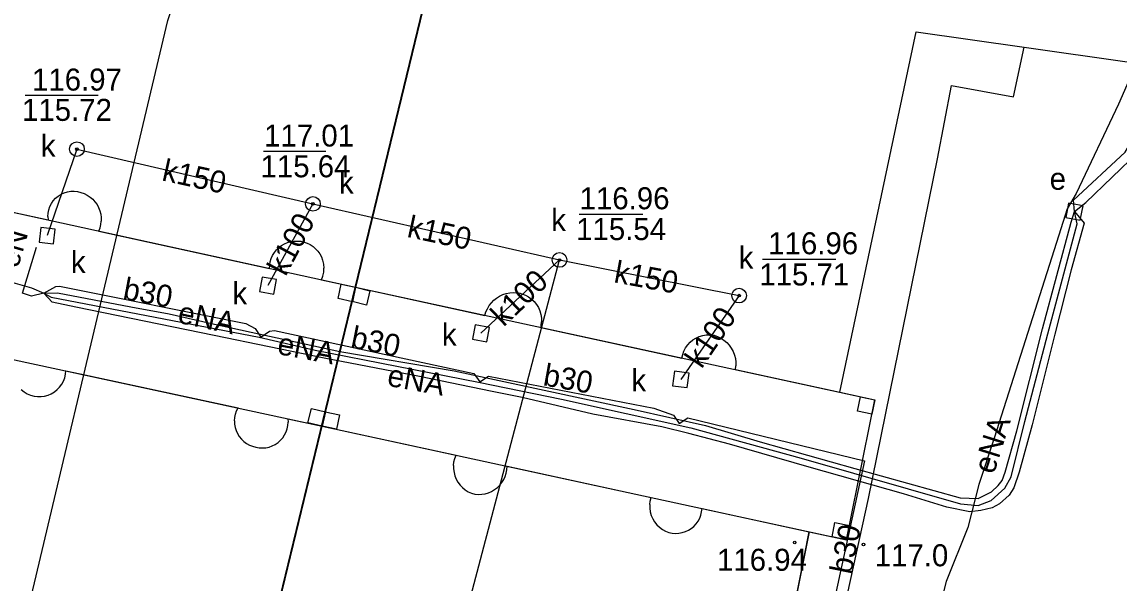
# Model space of a CAD drawing. Extents: x 6424617 to 6425697, y 5665845 to 5667190.
# Drawn here: x 6425428.81 to 6425466.22, y 5666525 to 5666544.12 of the extents above; entities that cross this region are included whole.
import ezdxf

# ---------------------------------------------------------------- set-up
doc = ezdxf.new("R2010")
doc.units = 0
for name, color, linetype in [('Warstwa 1', 7, 'Continuous'), ('Warstwa 12', 7, 'Continuous'), ('Warstwa 13', 7, 'Continuous'), ('Warstwa 14', 7, 'Continuous'), ('Warstwa 15', 7, 'Continuous'), ('Warstwa 25', 7, 'Continuous'), ('Warstwa 33', 7, 'Continuous'), ('Warstwa 4', 7, 'Continuous'), ('Warstwa 5', 7, 'Continuous'), ('Warstwa 6', 7, 'Continuous'), ('Warstwa 8', 7, 'Continuous'), ('Warstwa 9', 7, 'Continuous')]:
    doc.layers.add(name, color=color, linetype=linetype)

msp = doc.modelspace()

# ---------------------------------------------------------------- linework, layer by layer
at = {"layer": 'Warstwa 1'}
msp.add_line((6425426.498, 5666478.714), (6425446.546, 5666561.317), dxfattribs=at)
msp.add_line((6425426.498, 5666478.714), (6425446.546, 5666561.317), dxfattribs=at)
at = {"layer": 'Warstwa 12'}
for points in [[(6425380.898, 5666313.781), (6425400.051, 5666402.067), (6425408.909, 5666440.823), (6425416.154, 5666473.488), (6425420.109, 5666487.161), (6425420.685, 5666489.264), (6425421.019, 5666490.41), (6425433.788, 5666544.17), (6425438.345, 5666557.965), (6425447.158, 5666555.689), (6425449.696, 5666562.969)], [(6425464.702, 5666537.656), (6425464.675, 5666538.044), (6425466.427, 5666539.686), (6425466.835, 5666540.361), (6425473.065, 5666562.687)], [(6425464.702, 5666537.656), (6425465.091, 5666537.962), (6425466.887, 5666539.7), (6425467.175, 5666540.317), (6425473.425, 5666562.682)], [(6425467.242, 5666545.086), (6425466.733, 5666542.702), (6425466.567, 5666542.144), (6425466.207, 5666541.318), (6425464.76, 5666538.276), (6425464.45, 5666537.751), (6425464.173, 5666536.853), (6425461.959, 5666529.939), (6425461.44, 5666528.355), (6425461.062, 5666526.89), (6425460.33, 5666525.048), (6425459.721, 5666522.676), (6425458.623, 5666517.819), (6425457.064, 5666510.497), (6425456.807, 5666509.92), (6425456.473, 5666509.544), (6425455.928, 5666509.171), (6425455.043, 5666508.721), (6425454.006, 5666508.154), (6425449.423, 5666506.309), (6425447.519, 5666505.982), (6425446.295, 5666505.707), (6425444.189, 5666503.512), (6425436.064, 5666495.689)], [(6425430.685, 5666539.787), (6425429.669, 5666536.839)], [(6425430.685, 5666539.787), (6425438.733, 5666537.92), (6425447.141, 5666536.008)], [(6425416.711, 5666528.745), (6425418.224, 5666538.167), (6425429.138, 5666535.055), (6425429.552, 5666534.882)], [(6425438.733, 5666537.92), (6425437.2, 5666535.138)], [(6425464.702, 5666537.656), (6425465.028, 5666537.262), (6425464.588, 5666535.668), (6425464.032, 5666533.474), (6425463.255, 5666530.393), (6425462.815, 5666528.779), (6425462.639, 5666528.241), (6425462.476, 5666527.993), (6425462.142, 5666527.697), (6425461.9, 5666527.56), (6425461.509, 5666527.464), (6425461.139, 5666527.419), (6425460.351, 5666527.588), (6425458.876, 5666528.036), (6425455.657, 5666528.945), (6425452.936, 5666529.728), (6425451.55, 5666530.095), (6425450.633, 5666530.326), (6425448.278, 5666530.754), (6425445.864, 5666531.323), (6425444.847, 5666531.526), (6425442.363, 5666532.036), (6425439.12, 5666532.665), (6425435.359, 5666533.43), (6425430.65, 5666534.397), (6425429.842, 5666534.567), (6425429.552, 5666534.882)], [(6425429.552, 5666534.882), (6425429.804, 5666534.737), (6425436.898, 5666533.372), (6425438.813, 5666532.939), (6425444.38, 5666531.841), (6425447.204, 5666531.267), (6425451.622, 5666530.284), (6425455.38, 5666529.248), (6425460.812, 5666527.693), (6425461.421, 5666527.635), (6425461.863, 5666527.81), (6425462.329, 5666528.235), (6425462.543, 5666528.612), (6425463.006, 5666530.506), (6425463.792, 5666533.487), (6425464.798, 5666537.245), (6425464.702, 5666537.656)], [(6425429.552, 5666534.882), (6425430.016, 5666534.885), (6425432.52, 5666534.415), (6425433.828, 5666534.169), (6425435.373, 5666533.82), (6425439.653, 5666532.888), (6425443.545, 5666532.231), (6425449.69, 5666530.917), (6425452.123, 5666530.368), (6425453.987, 5666529.805), (6425457.216, 5666528.906), (6425460.805, 5666527.903), (6425461.424, 5666527.875), (6425461.877, 5666528.1), (6425462.1, 5666528.317), (6425462.232, 5666528.486), (6425462.335, 5666528.774), (6425462.732, 5666530.19), (6425463.614, 5666533.659), (6425464.586, 5666537.298), (6425464.702, 5666537.656)], [(6425429.552, 5666534.882), (6425429.137, 5666534.78), (6425428.826, 5666534.879), (6425429.305, 5666536.443)], [(6425407.795, 5666377.502), (6425413.082, 5666398.74), (6425423.493, 5666441.827), (6425434.167, 5666486.832), (6425447.141, 5666536.008)], [(6425447.141, 5666536.008), (6425444.461, 5666533.51)], [(6425447.141, 5666536.008), (6425453.267, 5666534.794)], [(6425429.552, 5666534.882), (6425429.964, 5666535.101), (6425430.085, 5666535.121), (6425436.44, 5666533.848), (6425436.761, 5666533.671), (6425436.96, 5666533.38)], [(6425453.267, 5666534.794), (6425451.282, 5666531.938)], [(6425436.96, 5666533.38), (6425437.252, 5666533.579), (6425437.427, 5666533.606), (6425444.225, 5666532.14), (6425444.428, 5666531.851)], [(6425444.428, 5666531.851), (6425444.717, 5666532.053), (6425450.353, 5666530.96), (6425451.023, 5666530.723), (6425451.218, 5666530.429)], [(6425451.218, 5666530.429), (6425451.512, 5666530.624), (6425457.542, 5666529.162), (6425456.393, 5666523.876), (6425454.252, 5666517.66)]]:
    msp.add_lwpolyline(points, dxfattribs=at)
at = {"layer": 'Warstwa 13'}
msp.add_circle((6425457.511, 5666526.308), 0.045, dxfattribs=at)
at = {"layer": 'Warstwa 14'}
for p, q in [((6425428.917, 5666541.627), (6425431.409, 5666541.627)), ((6425437.051, 5666539.714), (6425439.167, 5666539.714)), ((6425447.814, 5666537.573), (6425449.985, 5666537.573)), ((6425454.06, 5666536.032), (6425456.569, 5666536.032))]:
    msp.add_line(p, q, dxfattribs=at)
for centre in [(6425430.685, 5666539.787), (6425438.733, 5666537.92), (6425447.141, 5666536.008), (6425453.267, 5666534.794)]:
    msp.add_circle(centre, 0.045, dxfattribs=at)
at = {"layer": 'Warstwa 25'}
msp.add_circle((6425455.161, 5666526.381), 0.045, dxfattribs=at)
at = {"layer": 'Warstwa 33'}
for p, q in [((6425426.407, 5666538.096), (6425440.186, 5666535.076)), ((6425439.048, 5666530.345), (6425440.186, 5666535.076)), ((6425439.048, 5666530.345), (6425440.186, 5666535.076)), ((6425440.186, 5666535.076), (6425457.898, 5666531.242)), ((6425425.351, 5666533.3), (6425439.048, 5666530.345)), ((6425456.925, 5666526.467), (6425457.898, 5666531.242)), ((6425439.048, 5666530.345), (6425456.925, 5666526.467))]:
    msp.add_line(p, q, dxfattribs=at)
for points in [[(6425440.079, 5666534.587), (6425439.59, 5666534.694), (6425439.697, 5666535.183), (6425440.186, 5666535.076)], [(6425440.673, 5666534.959), (6425440.556, 5666534.472), (6425440.069, 5666534.589), (6425440.186, 5666535.076)], [(6425457.792, 5666530.754), (6425457.304, 5666530.86), (6425457.41, 5666531.348), (6425457.898, 5666531.242)], [(6425438.561, 5666530.462), (6425438.678, 5666530.949), (6425439.165, 5666530.832), (6425439.048, 5666530.345)], [(6425439.154, 5666530.833), (6425439.642, 5666530.727), (6425439.536, 5666530.239), (6425439.048, 5666530.345)], [(6425456.435, 5666526.567), (6425456.535, 5666527.057), (6425457.025, 5666526.957), (6425456.925, 5666526.467)]]:
    msp.add_lwpolyline(points, close=True, dxfattribs=at)
at = {"layer": 'Warstwa 4'}
for points in [[(6425464.9, 5666537.363), (6425464.995, 5666537.854), (6425464.504, 5666537.949), (6425464.409, 5666537.458)], [(6425429.45, 5666537.116), (6425429.392, 5666536.62), (6425429.888, 5666536.562), (6425429.946, 5666537.058)], [(6425436.997, 5666535.428), (6425436.91, 5666534.935), (6425437.403, 5666534.848), (6425437.49, 5666535.341)], [(6425444.752, 5666533.71), (6425444.261, 5666533.801), (6425444.17, 5666533.31), (6425444.661, 5666533.219)], [(6425451.068, 5666532.22), (6425451, 5666531.724), (6425451.496, 5666531.656), (6425451.564, 5666532.152)]]:
    msp.add_lwpolyline(points, close=True, dxfattribs=at)
for centre in [(6425430.685, 5666539.787), (6425438.733, 5666537.92), (6425447.141, 5666536.008), (6425453.267, 5666534.794)]:
    msp.add_circle(centre, 0.25, dxfattribs=at)
at = {"layer": 'Warstwa 6'}
for points in [[(6425412.836, 5666481.999), (6425414.841, 5666481.544), (6425426.498, 5666478.714), (6425446.546, 5666561.317), (6425434.889, 5666564.147), (6425438.183, 5666577.748), (6425436.256, 5666578.862)], [(6425445.943, 5666473.999), (6425449.122, 5666487.121), (6425471.272, 5666493.575), (6425489.08, 5666567.113), (6425449.85, 5666574.917), (6425446.546, 5666561.317), (6425426.498, 5666478.714)]]:
    msp.add_lwpolyline(points, close=True, dxfattribs=at)
for points in [[(6425456.703, 5666531.501), (6425459.304, 5666543.782), (6425462.987, 5666543.257), (6425466.579, 5666542.746), (6425468.099, 5666550.832), (6425426.818, 5666561.105), (6425426.239, 5666561.299), (6425425.664, 5666561.506), (6425425.094, 5666561.725), (6425424.53, 5666561.957), (6425423.97, 5666562.202), (6425423.417, 5666562.46), (6425422.869, 5666562.73), (6425422.328, 5666563.012), (6425421.793, 5666563.306)], [(6425455.66, 5666526.741), (6425453.028, 5666513.652), (6425431.999, 5666496.905), (6425431.589, 5666496.517), (6425431.195, 5666496.111), (6425430.819, 5666495.689), (6425430.462, 5666495.252), (6425430.123, 5666494.799), (6425429.805, 5666494.333), (6425429.506, 5666493.853), (6425429.229, 5666493.361), (6425428.972, 5666492.857), (6425428.722, 5666492.217)]]:
    msp.add_lwpolyline(points, dxfattribs=at)
at = {"layer": 'Warstwa 8'}
for p, q in [((6425456.703, 5666531.501), (6425459.304, 5666543.782)), ((6425459.304, 5666543.782), (6425462.987, 5666543.257)), ((6425462.987, 5666543.257), (6425466.579, 5666542.746)), ((6425429.879, 5666538.028), (6425429.958, 5666538.113)), ((6425429.958, 5666538.113), (6425430.047, 5666538.187)), ((6425430.047, 5666538.187), (6425430.145, 5666538.249)), ((6425430.145, 5666538.249), (6425430.25, 5666538.297)), ((6425430.25, 5666538.297), (6425430.361, 5666538.331)), ((6425430.361, 5666538.331), (6425430.475, 5666538.349)), ((6425430.475, 5666538.349), (6425430.591, 5666538.352)), ((6425430.591, 5666538.352), (6425430.706, 5666538.34)), ((6425430.706, 5666538.34), (6425430.819, 5666538.312)), ((6425430.819, 5666538.312), (6425430.93, 5666538.272)), ((6425430.93, 5666538.272), (6425431.034, 5666538.219)), ((6425431.034, 5666538.219), (6425431.132, 5666538.154)), ((6425431.132, 5666538.154), (6425431.221, 5666538.078)), ((6425426.407, 5666538.096), (6425429.698, 5666537.375)), ((6425429.722, 5666537.72), (6425429.761, 5666537.829)), ((6425429.761, 5666537.829), (6425429.813, 5666537.932)), ((6425429.813, 5666537.932), (6425429.879, 5666538.028)), ((6425431.221, 5666538.078), (6425431.3, 5666537.991)), ((6425431.3, 5666537.991), (6425431.369, 5666537.895)), ((6425431.369, 5666537.895), (6425431.425, 5666537.792)), ((6425431.425, 5666537.792), (6425431.468, 5666537.683)), ((6425429.691, 5666537.491), (6425429.699, 5666537.606)), ((6425429.691, 5666537.491), (6425429.698, 5666537.375)), ((6425429.699, 5666537.606), (6425429.722, 5666537.72)), ((6425431.468, 5666537.683), (6425431.497, 5666537.569)), ((6425431.497, 5666537.569), (6425431.513, 5666537.453)), ((6425431.513, 5666537.453), (6425431.514, 5666537.335)), ((6425431.434, 5666536.994), (6425431.475, 5666537.104)), ((6425431.434, 5666536.994), (6425433.091, 5666536.631)), ((6425431.475, 5666537.104), (6425431.501, 5666537.219)), ((6425431.501, 5666537.219), (6425431.514, 5666537.335)), ((6425433.091, 5666536.631), (6425437.251, 5666535.72)), ((6425437.867, 5666536.602), (6425437.977, 5666536.634)), ((6425437.977, 5666536.634), (6425438.09, 5666536.652)), ((6425438.09, 5666536.652), (6425438.205, 5666536.655)), ((6425438.205, 5666536.655), (6425438.319, 5666536.645)), ((6425438.319, 5666536.645), (6425438.431, 5666536.62)), ((6425438.431, 5666536.62), (6425438.539, 5666536.582)), ((6425437.358, 5666536.162), (6425437.417, 5666536.26)), ((6425437.417, 5666536.26), (6425437.489, 5666536.35)), ((6425437.489, 5666536.35), (6425437.571, 5666536.43)), ((6425437.571, 5666536.43), (6425437.662, 5666536.5)), ((6425437.662, 5666536.5), (6425437.761, 5666536.557)), ((6425437.761, 5666536.557), (6425437.867, 5666536.602)), ((6425438.539, 5666536.582), (6425438.642, 5666536.531)), ((6425438.642, 5666536.531), (6425438.737, 5666536.467)), ((6425438.737, 5666536.467), (6425438.824, 5666536.392)), ((6425438.824, 5666536.392), (6425438.901, 5666536.307)), ((6425438.901, 5666536.307), (6425438.967, 5666536.213)), ((6425437.257, 5666535.835), (6425437.277, 5666535.948)), ((6425437.277, 5666535.948), (6425437.311, 5666536.057)), ((6425437.311, 5666536.057), (6425437.358, 5666536.162)), ((6425438.967, 5666536.213), (6425439.02, 5666536.111)), ((6425439.02, 5666536.111), (6425439.061, 5666536.004)), ((6425439.061, 5666536.004), (6425439.094, 5666535.87)), ((6425439.094, 5666535.87), (6425439.107, 5666535.733)), ((6425437.251, 5666535.72), (6425437.257, 5666535.835)), ((6425439.073, 5666535.46), (6425439.1, 5666535.595)), ((6425439.1, 5666535.595), (6425439.107, 5666535.733)), ((6425439.026, 5666535.33), (6425439.073, 5666535.46)), ((6425439.026, 5666535.33), (6425440.186, 5666535.076)), ((6425440.186, 5666535.076), (6425444.599, 5666534.121)), ((6425444.995, 5666534.712), (6425445.098, 5666534.776)), ((6425445.098, 5666534.776), (6425445.208, 5666534.828)), ((6425445.208, 5666534.828), (6425445.323, 5666534.865)), ((6425445.323, 5666534.865), (6425445.442, 5666534.889)), ((6425445.442, 5666534.889), (6425445.562, 5666534.898)), ((6425445.562, 5666534.898), (6425445.683, 5666534.893)), ((6425445.683, 5666534.893), (6425445.803, 5666534.873)), ((6425445.803, 5666534.873), (6425445.862, 5666534.858)), ((6425445.862, 5666534.858), (6425445.978, 5666534.812)), ((6425445.978, 5666534.812), (6425446.087, 5666534.751)), ((6425446.087, 5666534.751), (6425446.188, 5666534.677)), ((6425444.682, 5666534.348), (6425444.743, 5666534.453)), ((6425444.743, 5666534.453), (6425444.817, 5666534.549)), ((6425444.817, 5666534.549), (6425444.901, 5666534.636)), ((6425444.901, 5666534.636), (6425444.995, 5666534.712)), ((6425446.188, 5666534.677), (6425446.278, 5666534.59)), ((6425446.278, 5666534.59), (6425446.356, 5666534.493)), ((6425446.356, 5666534.493), (6425446.421, 5666534.386)), ((6425446.421, 5666534.386), (6425446.472, 5666534.272)), ((6425444.599, 5666534.121), (6425444.634, 5666534.237)), ((6425444.634, 5666534.237), (6425444.682, 5666534.348)), ((6425446.472, 5666534.272), (6425446.508, 5666534.152)), ((6425446.508, 5666534.152), (6425446.528, 5666534.028)), ((6425446.528, 5666534.028), (6425446.532, 5666533.903)), ((6425446.506, 5666533.708), (6425446.513, 5666533.744)), ((6425446.506, 5666533.708), (6425451.317, 5666532.667)), ((6425446.513, 5666533.744), (6425446.52, 5666533.779)), ((6425446.52, 5666533.779), (6425446.532, 5666533.903)), ((6425451.597, 5666533.202), (6425451.691, 5666533.281)), ((6425451.691, 5666533.281), (6425451.795, 5666533.347)), ((6425451.795, 5666533.347), (6425451.907, 5666533.398)), ((6425451.907, 5666533.398), (6425452.024, 5666533.435)), ((6425452.024, 5666533.435), (6425452.145, 5666533.456)), ((6425452.145, 5666533.456), (6425452.268, 5666533.461)), ((6425452.268, 5666533.461), (6425452.39, 5666533.45)), ((6425452.39, 5666533.45), (6425452.411, 5666533.446)), ((6425452.411, 5666533.446), (6425452.529, 5666533.403)), ((6425452.529, 5666533.403), (6425452.642, 5666533.345)), ((6425452.642, 5666533.345), (6425452.746, 5666533.275)), ((6425452.746, 5666533.275), (6425452.842, 5666533.193)), ((6425451.344, 5666532.787), (6425451.386, 5666532.902)), ((6425451.386, 5666532.902), (6425451.443, 5666533.011)), ((6425451.443, 5666533.011), (6425451.514, 5666533.112)), ((6425451.514, 5666533.112), (6425451.597, 5666533.202)), ((6425452.842, 5666533.193), (6425452.927, 5666533.099)), ((6425452.927, 5666533.099), (6425453, 5666532.997)), ((6425453, 5666532.997), (6425453.061, 5666532.886)), ((6425453.061, 5666532.886), (6425453.107, 5666532.769)), ((6425451.317, 5666532.667), (6425451.344, 5666532.787)), ((6425453.107, 5666532.769), (6425453.14, 5666532.647)), ((6425453.14, 5666532.647), (6425453.158, 5666532.523)), ((6425453.158, 5666532.523), (6425453.16, 5666532.396)), ((6425430.294, 5666532.111), (6425430.306, 5666532.231)), ((6425430.306, 5666532.231), (6425430.797, 5666532.125)), ((6425430.797, 5666532.125), (6425436.18, 5666530.963)), ((6425453.148, 5666532.271), (6425453.16, 5666532.396)), ((6425453.148, 5666532.271), (6425456.703, 5666531.501)), ((6425430.093, 5666531.676), (6425430.164, 5666531.774)), ((6425430.164, 5666531.774), (6425430.222, 5666531.88)), ((6425430.222, 5666531.88), (6425430.266, 5666531.993)), ((6425430.266, 5666531.993), (6425430.294, 5666532.111)), ((6425428.785, 5666531.59), (6425428.882, 5666531.513)), ((6425428.882, 5666531.513), (6425428.989, 5666531.449)), ((6425428.989, 5666531.449), (6425429.103, 5666531.4)), ((6425429.103, 5666531.4), (6425429.222, 5666531.366)), ((6425429.583, 5666531.37), (6425429.7, 5666531.403)), ((6425429.7, 5666531.403), (6425429.811, 5666531.451)), ((6425429.811, 5666531.451), (6425429.914, 5666531.513)), ((6425429.914, 5666531.513), (6425430.009, 5666531.588)), ((6425430.009, 5666531.588), (6425430.093, 5666531.676)), ((6425429.222, 5666531.366), (6425429.342, 5666531.351)), ((6425429.342, 5666531.351), (6425429.463, 5666531.352)), ((6425429.463, 5666531.352), (6425429.583, 5666531.37)), ((6425436.058, 5666530.528), (6425436.068, 5666530.642)), ((6425436.068, 5666530.642), (6425436.091, 5666530.753)), ((6425436.091, 5666530.753), (6425436.129, 5666530.861)), ((6425436.129, 5666530.861), (6425436.18, 5666530.963)), ((6425436.058, 5666530.528), (6425436.063, 5666530.414)), ((6425436.063, 5666530.414), (6425436.082, 5666530.302)), ((6425436.082, 5666530.302), (6425436.116, 5666530.193)), ((6425437.817, 5666530.148), (6425437.853, 5666530.257)), ((6425437.853, 5666530.257), (6425437.876, 5666530.369)), ((6425437.876, 5666530.598), (6425439.048, 5666530.345)), ((6425437.876, 5666530.598), (6425437.883, 5666530.484)), ((6425437.876, 5666530.369), (6425437.883, 5666530.484)), ((6425439.048, 5666530.345), (6425443.617, 5666529.353)), ((6425436.116, 5666530.193), (6425436.163, 5666530.089)), ((6425436.163, 5666530.089), (6425436.222, 5666529.992)), ((6425436.222, 5666529.992), (6425436.294, 5666529.903)), ((6425436.294, 5666529.903), (6425436.376, 5666529.824)), ((6425437.628, 5666529.863), (6425437.703, 5666529.95)), ((6425437.703, 5666529.95), (6425437.766, 5666530.045)), ((6425437.766, 5666530.045), (6425437.817, 5666530.148)), ((6425436.376, 5666529.824), (6425436.468, 5666529.756)), ((6425436.468, 5666529.756), (6425436.567, 5666529.7)), ((6425436.567, 5666529.7), (6425436.673, 5666529.657)), ((6425436.673, 5666529.657), (6425436.783, 5666529.628)), ((6425436.783, 5666529.628), (6425436.896, 5666529.607)), ((6425436.896, 5666529.607), (6425437.01, 5666529.601)), ((6425437.01, 5666529.601), (6425437.124, 5666529.61)), ((6425437.124, 5666529.61), (6425437.237, 5666529.633)), ((6425437.237, 5666529.633), (6425437.345, 5666529.671)), ((6425437.345, 5666529.671), (6425437.447, 5666529.723)), ((6425437.447, 5666529.723), (6425437.542, 5666529.787)), ((6425437.542, 5666529.787), (6425437.628, 5666529.863)), ((6425443.543, 5666529.124), (6425443.573, 5666529.241)), ((6425443.573, 5666529.241), (6425443.617, 5666529.353)), ((6425443.528, 5666529.005), (6425443.543, 5666529.124)), ((6425443.528, 5666529.005), (6425443.528, 5666528.884)), ((6425443.528, 5666528.884), (6425443.544, 5666528.765)), ((6425443.544, 5666528.765), (6425443.575, 5666528.649)), ((6425445.326, 5666528.744), (6425445.348, 5666528.859)), ((6425445.348, 5666528.859), (6425445.356, 5666528.976)), ((6425445.356, 5666528.976), (6425450.268, 5666527.911)), ((6425443.575, 5666528.649), (6425443.62, 5666528.537)), ((6425443.62, 5666528.537), (6425443.679, 5666528.432)), ((6425443.679, 5666528.432), (6425443.751, 5666528.335)), ((6425445.105, 5666528.334), (6425445.179, 5666528.425)), ((6425445.179, 5666528.425), (6425445.241, 5666528.525)), ((6425445.241, 5666528.525), (6425445.29, 5666528.632)), ((6425445.29, 5666528.632), (6425445.326, 5666528.744)), ((6425443.751, 5666528.335), (6425443.834, 5666528.249)), ((6425443.834, 5666528.249), (6425443.928, 5666528.173)), ((6425443.928, 5666528.173), (6425444.031, 5666528.11)), ((6425444.031, 5666528.11), (6425444.141, 5666528.061)), ((6425444.141, 5666528.061), (6425444.256, 5666528.026)), ((6425444.256, 5666528.026), (6425444.373, 5666528.017)), ((6425444.373, 5666528.017), (6425444.49, 5666528.022)), ((6425444.49, 5666528.022), (6425444.606, 5666528.041)), ((6425444.606, 5666528.041), (6425444.719, 5666528.075)), ((6425444.719, 5666528.075), (6425444.827, 5666528.121)), ((6425444.827, 5666528.121), (6425444.928, 5666528.181)), ((6425444.928, 5666528.181), (6425445.021, 5666528.252)), ((6425445.021, 5666528.252), (6425445.105, 5666528.334)), ((6425450.219, 5666527.668), (6425450.236, 5666527.791)), ((6425450.219, 5666527.668), (6425450.22, 5666527.544)), ((6425450.236, 5666527.791), (6425450.268, 5666527.911)), ((6425450.22, 5666527.544), (6425450.237, 5666527.421)), ((6425450.237, 5666527.421), (6425450.27, 5666527.301)), ((6425450.27, 5666527.301), (6425450.319, 5666527.187)), ((6425451.921, 5666527.204), (6425451.962, 5666527.31)), ((6425451.962, 5666527.31), (6425451.989, 5666527.421)), ((6425451.989, 5666527.421), (6425452.002, 5666527.534)), ((6425452.002, 5666527.534), (6425455.66, 5666526.741)), ((6425450.319, 5666527.187), (6425450.383, 5666527.081)), ((6425450.383, 5666527.081), (6425450.46, 5666526.984)), ((6425450.46, 5666526.984), (6425450.55, 5666526.898)), ((6425450.55, 5666526.898), (6425450.65, 5666526.824)), ((6425451.634, 5666526.857), (6425451.722, 5666526.929)), ((6425451.722, 5666526.929), (6425451.8, 5666527.012)), ((6425451.8, 5666527.012), (6425451.866, 5666527.104)), ((6425451.866, 5666527.104), (6425451.921, 5666527.204)), ((6425450.65, 5666526.824), (6425450.759, 5666526.765)), ((6425450.759, 5666526.765), (6425450.875, 5666526.721)), ((6425450.875, 5666526.721), (6425450.986, 5666526.698)), ((6425450.986, 5666526.698), (6425451.1, 5666526.689)), ((6425451.1, 5666526.689), (6425451.214, 5666526.694)), ((6425451.214, 5666526.694), (6425451.326, 5666526.714)), ((6425451.326, 5666526.714), (6425451.434, 5666526.749)), ((6425451.434, 5666526.749), (6425451.537, 5666526.796)), ((6425451.537, 5666526.796), (6425451.634, 5666526.857)), ((6425453.028, 5666513.652), (6425455.66, 5666526.741))]:
    msp.add_line(p, q, dxfattribs=at)
at = {"layer": 'Warstwa 9'}
for p, q in [((6425456.703, 5666531.501), (6425459.304, 5666543.782)), ((6425459.304, 5666543.782), (6425462.987, 5666543.257)), ((6425462.625, 5666541.57), (6425462.987, 5666543.257)), ((6425460.027, 5666539.456), (6425460.508, 5666541.956)), ((6425460.508, 5666541.956), (6425462.625, 5666541.57)), ((6425457.675, 5666527.878), (6425460.027, 5666539.456)), ((6425456.703, 5666531.501), (6425457.898, 5666531.242)), ((6425456.925, 5666526.467), (6425457.898, 5666531.242)), ((6425455.788, 5666519.274), (6425457.675, 5666527.878)), ((6425453.028, 5666513.652), (6425455.66, 5666526.741)), ((6425455.66, 5666526.741), (6425456.925, 5666526.467))]:
    msp.add_line(p, q, dxfattribs=at)

# ---------------------------------------------------------------- texts
at = {"layer": 'Warstwa 13'}
for s, rotation, p in [('k150', 347.6307, (6425433.55, 5666538.725)), ('k100', 61.8221, (6425437.799, 5666535.422)), ('k150', 347.8828, (6425441.911, 5666536.8)), ('eN', 73.6709, (6425428.668, 5666535.694)), ('k150', 349.4813, (6425448.966, 5666535.252)), ('k100', 43.6708, (6425445.236, 5666533.705)), ('b30', 349.3667, (6425432.219, 5666534.681)), ('eNA', 347.9802, (6425434.085, 5666533.877)), ('k100', 55.8978, (6425451.987, 5666532.274)), ('b30', 348.5188, (6425439.984, 5666533.029)), ('eNA', 349.2808, (6425437.483, 5666532.809)), ('b30', 349.7162, (6425446.55, 5666531.743)), ('eNA', 349.7105, (6425441.233, 5666531.726)), ('eNA', 72.5422, (6425461.951, 5666528.676)), ('b30', 78.4207, (6425457.09, 5666525.264))]:
    msp.add_text(s, height=0.75, rotation=rotation, dxfattribs=at).set_placement(p)
msp.add_text('117.0', height=0.75, dxfattribs=at).set_placement((6425457.89, 5666525.567))
at = {"layer": 'Warstwa 14'}
for s, p in [('115.72', (6425428.811, 5666540.75)), ('115.64', (6425436.945, 5666538.827)), ('115.54', (6425447.708, 5666536.686)), ('115.71', (6425453.954, 5666535.139))]:
    msp.add_text(s, height=0.75, dxfattribs=at).set_placement(p)
at = {"layer": 'Warstwa 15'}
for s, p in [('116.97', (6425429.152, 5666541.783)), ('117.01', (6425437.067, 5666539.875)), ('116.96', (6425447.826, 5666537.737)), ('116.96', (6425454.258, 5666536.203))]:
    msp.add_text(s, height=0.75, dxfattribs=at).set_placement(p)
at = {"layer": 'Warstwa 25'}
msp.add_text('116.94', height=0.75, dxfattribs=at).set_placement((6425452.512, 5666525.414))
at = {"layer": 'Warstwa 5'}
for s, p in [('k', (6425429.453, 5666539.529)), ('k', (6425439.62, 5666538.273)), ('e', (6425463.856, 5666538.402)), ('k', (6425446.858, 5666536.997)), ('k', (6425430.479, 5666535.564)), ('k', (6425453.25, 5666535.715)), ('k', (6425435.986, 5666534.498)), ('k', (6425443.13, 5666533.091)), ('k', (6425449.592, 5666531.533))]:
    msp.add_text(s, height=0.75, dxfattribs=at).set_placement(p)

doc.saveas('drawing.dxf')
